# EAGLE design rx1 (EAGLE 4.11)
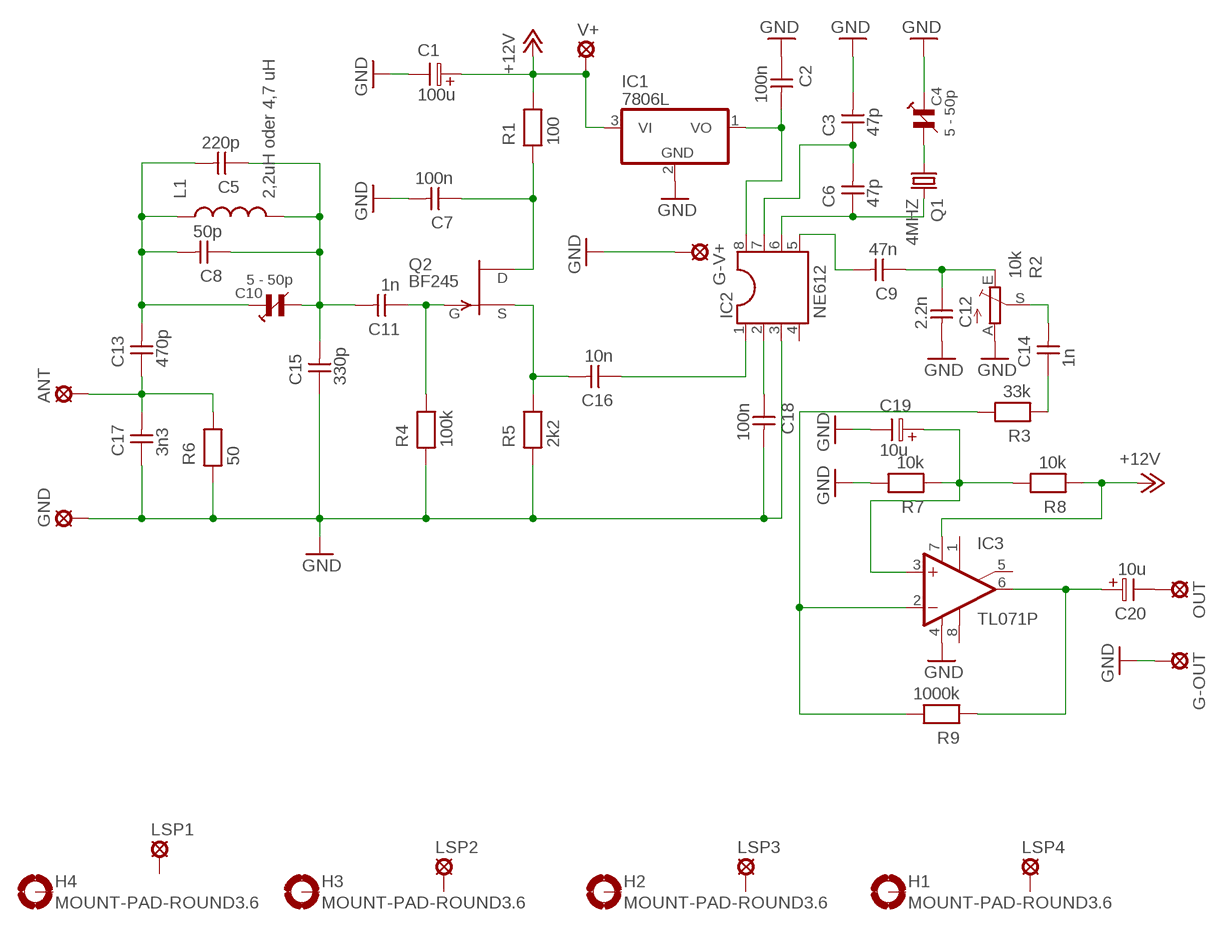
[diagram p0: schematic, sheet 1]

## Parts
ANT  MCS10B  [MCS10B]
C1  100u  ELC-2,5L  [ES-2,5L]
C2  100n  CAPNP-5  [C-5]
C3  47p  CAPNP-2,5  [C-2,5]
C4  5 - 50p  808/1  [808/1]
C5  220p  CAPNP-2,5  [C-2,5]
C6  47p  CAPNP-2,5  [C-2,5]
C7  100n  CAPNP-5  [C-5]
C8  50p  CAPNP-2,5  [C-2,5]
C9  47n  CAPNP-5  [C-5]
C10  5 - 50p  808/1  [808/1]
C11  1n  CAPNP-5  [C-5]
C12  2.2n  CAPNP-5  [C-5]
C13  470p  CAPNP-5  [C-5]
C14  1n  CAPNP-5  [C-5]
C15  330p  CAPNP-5  [C-5]
C16  10n  CAPNP-5  [C-5]
C17  3n3  CAPNP-5  [C-5]
C18  100n  CAPNP-5  [C-5]
C19  10u  ELC-2,5L  [ES-2,5L]
C20  10u  ELC-2,5L  [ES-2,5L]
G-OUT  MCS10B  [MCS10B]
G-V+  MCS10B  [MCS10B]
GND  MCS10B  [MCS10B]
H1  MOUNT-PAD-ROUND3.6  [3,6-PAD]
H2  MOUNT-PAD-ROUND3.6  [3,6-PAD]
H3  MOUNT-PAD-ROUND3.6  [3,6-PAD]
H4  MOUNT-PAD-ROUND3.6  [3,6-PAD]
IC1  7806L  [TO92]
IC2  NE612  DIL8S  [SOCKED-08]
IC3  TL071P  [DIL08]
L1  2,2uH oder 4,7 uH  L-12,5  [L-12,5]
LSP1  LSP10  [LSP10]
LSP2  LSP10  [LSP10]
LSP3  LSP10  [LSP10]
LSP4  LSP10  [LSP10]
OUT  MCS10B  [MCS10B]
Q1  4MHZ  CRYTALHC18U-V  [HC18U-V]
Q2  BF245  [TO92]
R1  100  RESEU-10  [R-10]
R2  10k  TRIM_EU-LI10  [LI10]
R3  33k  RESEU-10  [R-10]
R4  100k  RESEU-10  [R-10]
R5  2k2  RESEU-10  [R-10]
R6  50  RESEU-10  [R-10]
R7  10k  RESEU-10  [R-10]
R8  10k  RESEU-10  [R-10]
R9  1000k  RESEU-10  [R-10]
V+  MCS10B  [MCS10B]

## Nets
+12V: C1.1 IC1.3(VI) IC3.7(V+) R1.2 R8.1 V+.MP
GND: C1.2 C2.1 C3.2 C4.1 C7.2 C12.2 C15.1 C17.1 C18.2 C19.2 G-OUT.MP G-V+.MP GND.MP IC1.2(GND) IC2.3 IC3.4(V-) R2.A R4.1 R5.1 R6.1 R7.2
N$1: C5.2 C8.2 C10.1 C13.2 L1.1
N$2: ANT.MP C13.1 C17.2 R6.2
N$3: C5.1 C8.1 C10.2 C11.2 C15.2 L1.2
N$4: C11.1 Q2.3(G) R4.2
N$6: C16.2 Q2.2(S) R5.2
N$7: C7.1 Q2.1(D) R1.1
N$8: C2.2 IC1.1(VO) IC2.8
N$9: C16.1 IC2.1
N$10: C18.1 IC2.2
N$11: C4.2 Q1.1
N$12: C3.1 C6.2 IC2.7
N$13: C6.1 IC2.6 Q1.2
N$14: C9.2 IC2.5
N$15: C9.1 C12.1 R2.E
N$16: C14.1 R3.1
N$17: C14.2 R2.S
N$18: IC3.2(-IN) R3.2 R9.2
N$19: C20.1 IC3.6(OUT) R9.1
N$20: C19.1 IC3.3(+IN) R7.1 R8.2
N$22: C20.2 OUT.MP
Unconnected: C4.3 C10.3 H1.B3,6(MOUNT) H2.B3,6(MOUNT) H3.B3,6(MOUNT) H4.B3,6(MOUNT) IC2.4 IC3.1(ON1) IC3.5(ON2) IC3.8(OPT) LSP1.MP LSP2.MP LSP3.MP LSP4.MP

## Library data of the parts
ANT G-OUT G-V+ GND OUT V+ = solpad:MCS10B: SOLDER PAD
C1 C19 C20 = discrete:ELC-2,5L
C2 C7 C9 C11-C18 = discrete:CAPNP-5
C3 C5 C6 C8 = discrete:CAPNP-2,5
C4 C10 = Cap-Dreh:808/1
H1-H4 = holes:MOUNT-PAD-ROUND: MOUNTING PAD, round
IC1 = linear:78*: Positive VOLTAGE REGULATOR
IC2 = ic-package:DIL8: Dual In Line
IC3 = linear:TL071: OP AMP
L1 = discrete:L-12,5
LSP1-LSP4 = solpad:LSP10: SOLDER PAD
Q1 = crystal:CRYTAL: CRYSTAL
Q2 = transistor-fet:BF245: N-Channel Junction FET
R1 R3-R9 = discrete:RESEU-10
R2 = pot:TRIM_EU-: POTENTIOMETER

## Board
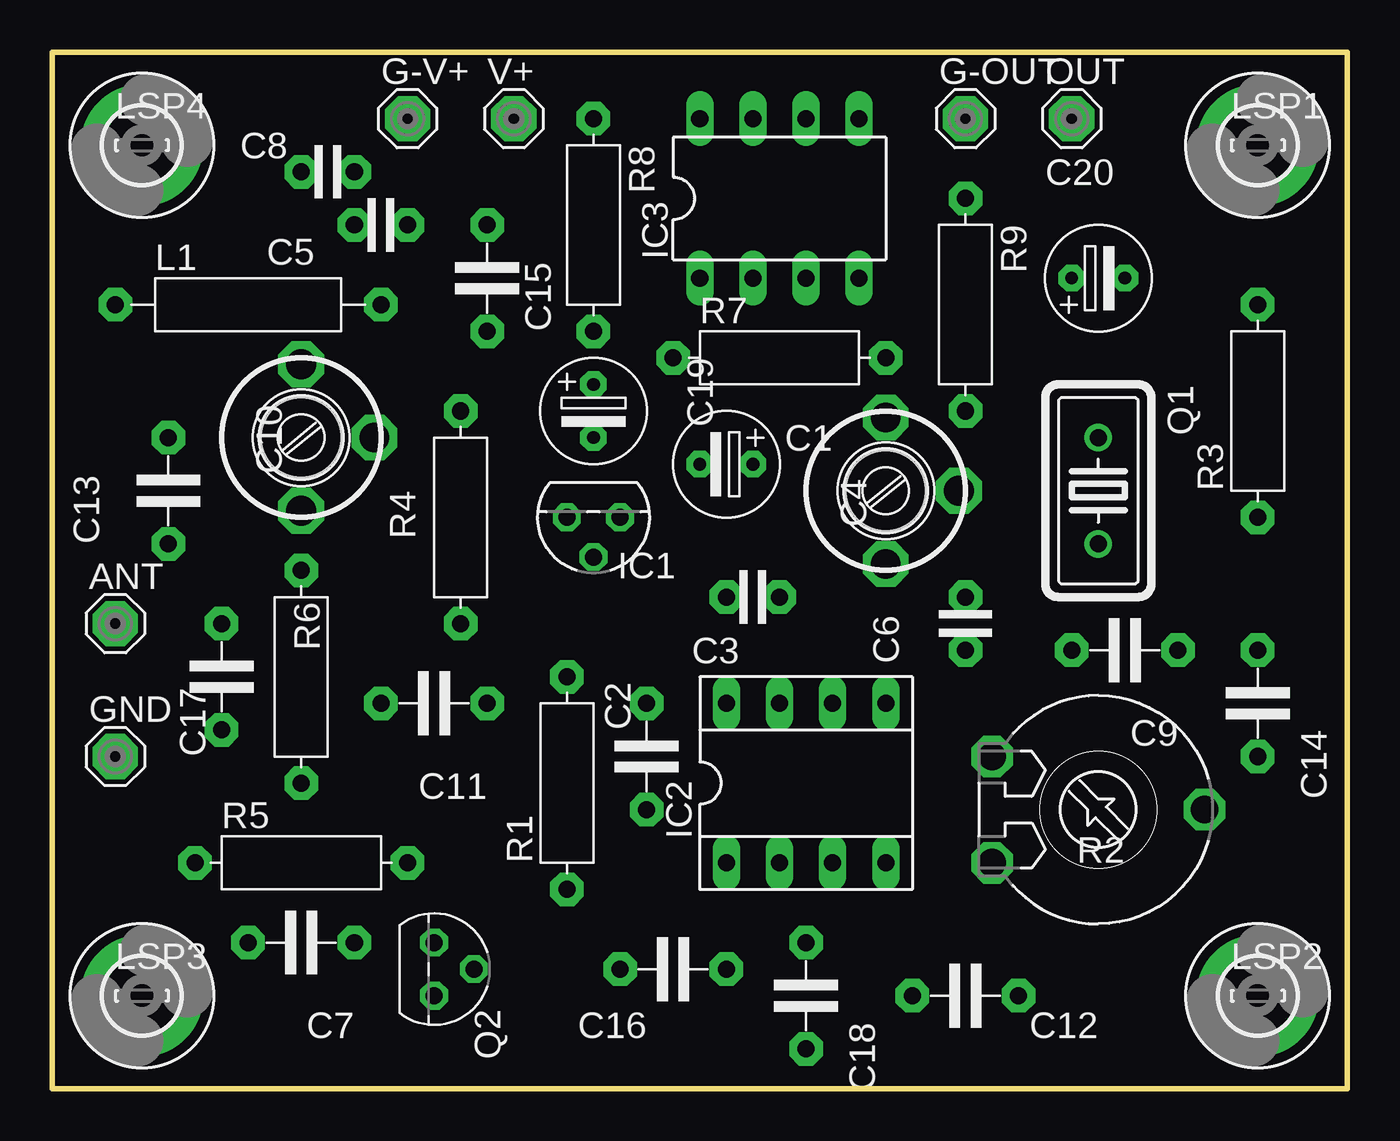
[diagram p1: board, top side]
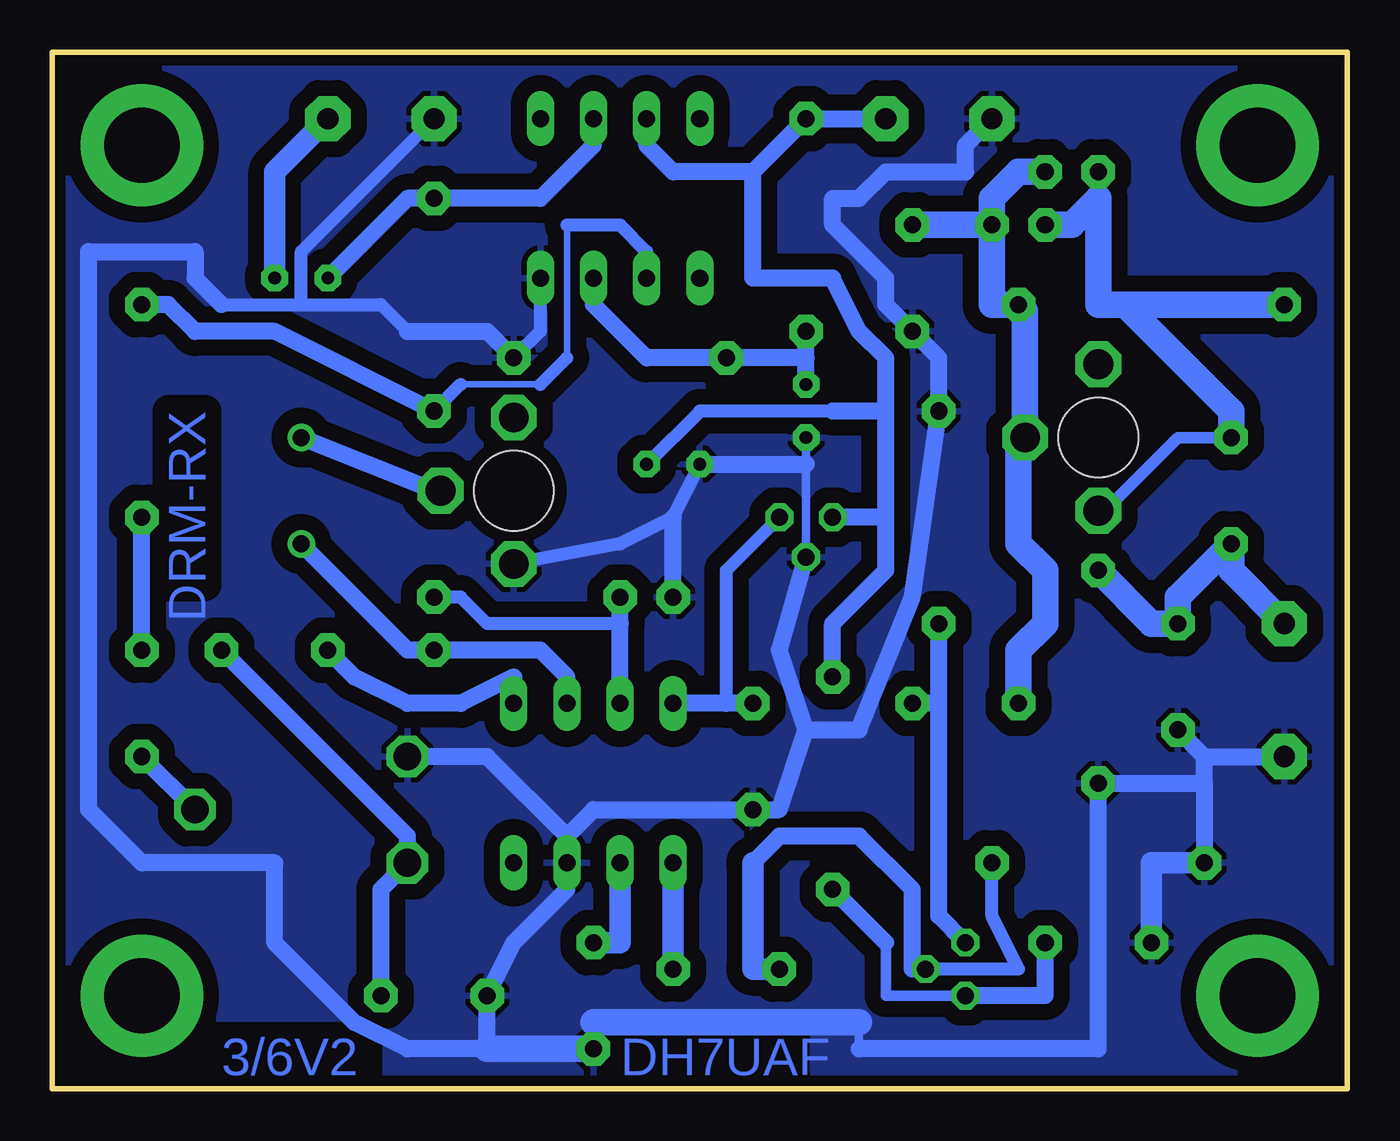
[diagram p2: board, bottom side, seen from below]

Size 61.9 x 49.52 mm. Coordinates in mm from the lower left corner, seen from the top.
Outline: 0,0 61.9,0 61.9,49.52 0,49.52 0,0
Copper layers (1*16): Top 0.035mm / dielectric 1.5mm / Bottom 0.035mm
Design rules "default": minimum track width 10mil, minimum drill 24mil, track to track 30mil, track to pad 30mil, pad to pad 8mil, via to via 8mil, smd to smd 8mil, copper to edge 20mil, drill to drill 8mil, minimum pad ring 10mil, minimum via ring 8mil, stop-mask expansion 4mil, vias tented up to drill 0mil, thermal gap 10mil

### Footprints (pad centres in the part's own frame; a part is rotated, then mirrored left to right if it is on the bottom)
MCS10B = drill 1.016 pad 2.159 octagon: MP 0,0
ES-2,5L = drill 0.61 pad 1.27 octagon: 1 0,0; 2 2.54,0
C-5 = drill 0.813 pad 1.6 octagon: 1 -2.54,0; 2 2.54,0
C-2,5 = drill 0.813 pad 1.6 octagon: 1 -1.27,0; 2 1.27,0
808/1 = drill 1.422 pad 2.184 octagon: 1 -3.5,0; 2 0,-3.5; 3 3.5,0 | hole 3.81: 0,0
3,6-PAD = drill 3.6 pad 5.842 round: B3,6 0,0
TO92 = drill 0.813 octagon: 1 -1.27,0; 2 0,1.905; 3 1.27,0
SOCKED-08 = drill 0.813 long: 1 -3.81,-3.81; 2 -1.27,-3.81; 3 1.27,-3.81; 4 3.81,-3.81; 5 3.81,3.81; 6 1.27,3.81; 7 -1.27,3.81; 8 -3.81,3.81
DIL08 = drill 0.813 long: 1 -3.81,-3.81; 2 -1.27,-3.81; 3 1.27,-3.81; 4 3.81,-3.81; 5 3.81,3.81; 6 1.27,3.81; 7 -1.27,3.81; 8 -3.81,3.81
L-12,5 = drill 0.813 pad 1.6 octagon: 1 -6.35,0; 2 6.35,0
LSP10 = drill 1.016 pad 2.159 octagon: MP 0,0
HC18U-V = drill 0.813 round: 1 -2.54,0; 2 2.54,0
TO92' = drill 0.813 octagon: 1 1.27,0; 2 0,1.905; 3 -1.27,0
R-10 = drill 0.813 pad 1.6 octagon: 1 -5.08,0; 2 5.08,0
LI10 = drill 1.321 octagon: A -2.54,-5.08; E 2.54,-5.08; S 0,5.08

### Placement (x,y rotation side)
ANT  3.01,22.22 0 top
C1  33.49,29.84 180 top
C2  28.41,15.87 90 top
C3  33.49,23.49 180 top
C4  39.84,28.57 90 top
C5  15.71,41.27 180 top
C6  43.65,22.22 90 top
C7  11.9,6.98 180 top
C8  13.17,43.81 180 top
C9  51.27,20.95 180 top
C10  11.9,31.11 90 top
C11  18.25,18.41 180 top
C12  43.65,4.44 180 top
C13  5.55,28.57 90 top
C14  57.62,18.41 270 top
C15  20.79,38.73 90 top
C16  29.68,5.71 180 top
C17  8.09,19.68 90 top
C18  36.03,4.44 270 top
C19  25.87,33.65 270 top
C20  48.73,38.73 0 top
G-OUT  43.65,46.35 0 top
G-V+  16.98,46.35 0 top
GND  3.01,15.87 0 top
H1  4.28,4.44 0 top
H2  4.28,45.08 0 top
H3  57.62,45.08 0 top
H4  57.62,4.44 0 top
IC1  25.87,27.3 180 top
IC2  36.03,14.6 0 top
IC3  34.76,42.54 0 top
L1  9.36,37.46 0 top
LSP1  57.62,45.08 0 top
LSP2  57.62,4.44 0 top
LSP3  4.28,4.44 0 top
LSP4  4.28,45.08 0 top
OUT  48.73,46.35 0 top
Q1  50,28.57 270 top
Q2  BF245  [TO92']  18.25,5.71 270 top
R1  24.6,14.6 90 top
R2  50,13.33 270 top
R3  57.62,32.38 90 top
R4  19.52,27.3 270 top
R5  11.9,10.79 0 top
R6  11.9,19.68 90 top
R7  34.76,34.92 0 top
R8  25.87,41.27 270 top
R9  43.65,37.46 270 top
V+  22.06,46.35 0 top

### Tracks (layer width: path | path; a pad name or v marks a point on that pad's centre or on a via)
+12V
  Bottom 0.61: C1.1 30.95,32.38 24.6,32.38
  Bottom 0.813: 28.41,43.81 32.22,43.81 33.49,45.08 IC3.7 | 28.41,43.81 R8.1 V+.MP | R1.2 24.6,22.22 22.06,24.76 22.06,27.3 | 22.06,32.38 22.06,34.92 23.33,36.19 24.6,38.73 28.41,38.73 28.41,43.81 | 22.06,32.38 24.6,32.38 | 22.06,27.3 22.06,32.38 | 22.06,27.3 IC1.3
GND
  Bottom 0.406: 25.87,24.76 IC1.2 C19.2 | 23.33,1.9 23.33,3.17 | 36.03,3.17 C18.2
  Bottom 0.61: R7.2 38.57,36.19 IC3.4 | G-OUT.MP 50,40 50,37.46 | C4.1 34.76,26.03 32.22,27.3 C1.2 | 44.92,36.19 46.19,37.46 50,37.46 | 53.81,37.46 50,37.46
  Bottom 0.813: 6.82,14.6 6.82,15.87 | 6.82,14.6 R5.1 | 6.82,15.87 C17.1 | 6.82,14.6 R6.1 11.9,1.9 23.33,1.9 | 6.82,15.87 GND.MP | C1.2 25.87,29.84 | 37.3,12.06 36.03,13.33 C2.1 27.14,13.33 25.87,17.14 | R2.A 41.11,15.87 37.3,12.06 | 37.3,12.06 IC2.3 37.3,9.52 39.84,6.98 C12.2 41.11,1.9 44.92,1.9 47.46,3.17 51.27,6.98 51.27,10.79 57.62,10.79 60.16,13.33 60.16,40 55.08,40 55.08,38.73 53.81,37.46 | G-V+.MP 18.25,45.08 18.25,43.81 22.06,43.81 23.33,42.54 24.6,42.54 24.6,41.27 22.06,38.73 22.06,37.46 C15.1 19.52,34.92 R4.1 20.79,23.49 23.33,17.14 25.87,17.14 | R7.2 41.11,36.19 44.92,36.19 | C3.2 32.22,27.3 | IC1.2 27.14,20.95 25.87,17.14
  Bottom 1.016: C7.2 9.36,10.79 R5.1
  Bottom 1.27: C18.2 41.11,1.9 | 23.33,3.17 36.03,3.17
  pour Bottom: -2.07,52.7 -2.07,-3.18 65.24,-3.18 63.97,-3.18 63.97,52.7
N$1
  Bottom 0.406: 11.9,42.54 C8.2
  Bottom 0.561: C13.2 8.09,31.11 11.9,27.3
  Bottom 1.27: C5.2 13.17,41.27 11.9,42.54 11.9,37.46 10.63,37.46 | 10.63,37.46 L1.1 | 10.63,37.46 5.55,32.38 C13.2 | C10.1 11.9,27.3
N$2
  Bottom 1.27: R6.2 9.36,22.22 C17.2 8.09,23.49 C13.1 5.55,24.76 ANT.MP
N$3
  Bottom 0.813: 15.71,31.11 C10.2 | 15.4,37.15 L1.2
  Bottom 1.27: C11.2 15.71,20.95 14.44,22.22 14.44,24.76 15.71,26.03 15.71,31.11 | C10.2 15.4,37.15 | C5.1 C15.2 | C5.1 16.98,37.46 L1.2 | C8.1 15.71,43.81 16.98,42.54 C5.1
N$4
  Bottom 0.813: 19.52,18.41 R4.2 | 19.52,18.41 C11.1 | Q2.3 19.52,8.25 19.52,18.41
N$6
  Bottom 0.61: Q2.2 15.71,5.71 16.98,8.25 R5.2
  Bottom 0.813: 28.41,10.79 27.14,12.06 23.33,12.06 20.79,9.52 20.79,5.71 Q2.2
  Bottom 1.016: 28.41,10.79 28.41,5.71 C16.2
N$7
  Bottom 0.511: Q2.1 22.06,4.44 22.06,6.98
  Bottom 0.813: C7.1 14.44,4.44 15.71,4.44 Q2.1 | 22.06,6.98 R1.1
N$8
  Bottom 0.61: IC1.1 29.68,24.76 29.68,18.41
  Bottom 0.813: C2.2 29.68,18.41 IC2.8
N$9
  Bottom 1.016: IC2.1 32.22,9.52 C16.1
N$10
  Bottom 1.016: IC2.2 34.76,6.98 C18.1
N$11
  Bottom 0.406: C4.2 43.65,28.57
  Bottom 0.813: 43.65,28.57 Q1.1
N$12
  Bottom 0.61: C6.2 42.38,23.49 41.11,22.22 34.76,22.22
  Bottom 0.813: IC2.7 34.76,22.22 C3.1
N$13
  Bottom 0.813: IC2.6 37.3,19.68 38.57,20.95 C6.1 44.92,20.95 Q1.2
N$14
  Bottom 0.813: C9.2 47.46,19.68 44.92,18.41 42.38,18.41 39.84,19.68 IC2.5
N$15
  Bottom 0.813: C12.1 46.19,9.52 R2.E 44.92,12.06 C9.1
N$16
  Bottom 0.813: C14.1 R3.1
N$17
  Bottom 0.813: R2.S C14.2
N$18
  Bottom 0.305: 37.3,34.92 37.3,41.27 | 38.57,33.65 42.38,33.65
  Bottom 0.61: 37.3,41.27 34.76,41.27 33.49,40 IC3.2 | 37.3,34.92 38.57,33.65 | 42.38,33.65 R9.2
  Bottom 0.813: R3.2 56.35,37.46 55.08,36.19 51.27,36.19 R9.2
N$19
  Bottom 0.813: C20.1 44.92,42.54 R9.1 38.57,42.54 36.03,45.08 IC3.6
N$20
  Bottom 0.813: 25.87,34.92 R8.2 | C19.1 25.87,34.92 | IC3.3 36.03,37.46 33.49,34.92 R7.1 25.87,34.92
N$22
  Bottom 1.016: C20.2 51.27,43.81 OUT.MP

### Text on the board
Bottom: DRM-RX | DH7UAF | 3/6V2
